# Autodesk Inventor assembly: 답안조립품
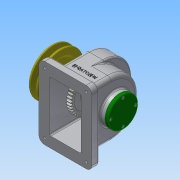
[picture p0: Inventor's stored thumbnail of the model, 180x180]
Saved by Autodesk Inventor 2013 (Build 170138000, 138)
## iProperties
Created: 2017-11
Part Number: 답안조립품
Document SubType Name: Assembly
Designer: Administrator
Author: Administrator
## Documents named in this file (14)
- C:\Users\Administrator\Desktop\471108V1021\답안조립품.iam
- C:\Users\Administrator\Desktop\471108V1021\V-벨트풀리.ipt
- C:\Users\Administrator\Desktop\471108V1021\뒤커버.ipt
- C:\Users\Administrator\Desktop\471108V1021\멈춤나사 - M4 x 10.ipt
- 멈춤나사 - M4 x 10.ipt
- C:\Users\Administrator\Desktop\471108V1021\베어링 6002.ipt
- C:\Users\Administrator\Desktop\471108V1021\본체.ipt
- C:\Users\Administrator\Desktop\471108V1021\볼트 M3 x 8.ipt
- C:\Users\Administrator\Desktop\471108V1021\스퍼기어.ipt
- C:\Users\Administrator\Desktop\471108V1021\앞커버.ipt
- C:\Users\Administrator\Desktop\471108V1021\오일 실 15 30 7.ipt
- C:\Users\Administrator\Desktop\471108V1021\축.ipt
- C:\Users\Administrator\Desktop\471108V1021\키 - 5 x 5 x 18.ipt
- C:\Users\Administrator\Desktop\471108V1021\키 - 6 x 6 x 22.ipt
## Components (1 placed, 1 different names)
1. V-벨트풀리:1
